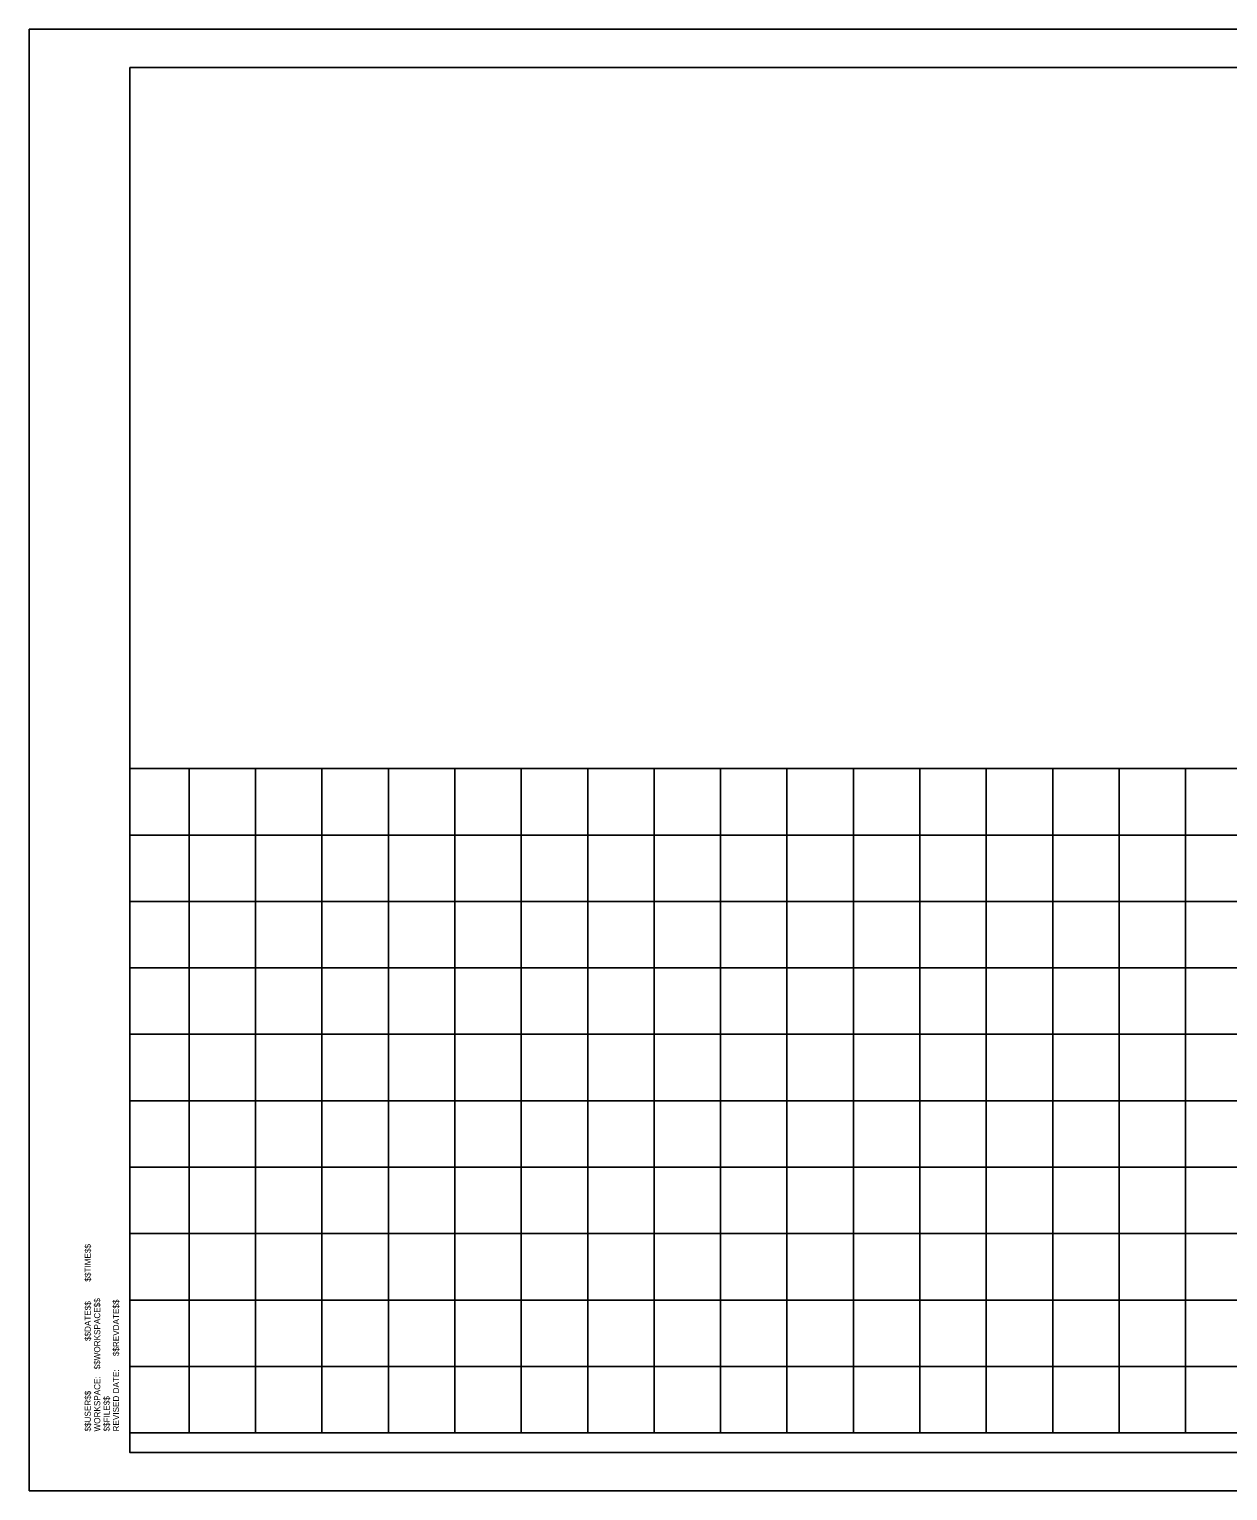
# Model space of a CAD drawing. Extents: x 0 to 1228740, y 0 to 152440.
# Drawn here: x 0 to 18.04, y 0 to 22 of the extents above; entities that cross this region are included whole.
import ezdxf

# ---------------------------------------------------------------- set-up
doc = ezdxf.new("R2010")
doc.units = 0
for name, color, linetype in [('G-TBLK', 7, 'Continuous'), ('R_Border', 7, 'Continuous'), ('R_Grid', 7, 'Continuous'), ('R_No Plot', 7, 'Continuous')]:
    doc.layers.add(name, color=color, linetype=linetype)

msp = doc.modelspace()

# ---------------------------------------------------------------- linework, layer by layer
at = {"layer": 'R_Border'}
for p, q in [((1.516, 21.423), (33.423, 21.423)), ((1.516, 0.577), (1.516, 21.423)), ((33.423, 0.577), (1.516, 0.577))]:
    msp.add_line(p, q, dxfattribs=at)
msp.add_lwpolyline([(34, 22), (0, 22), (0, 0), (34, 0)], close=True, dxfattribs=at)
at = {"layer": 'R_Grid'}
for p, q in [((33.423, 10.871), (1.516, 10.871)), ((2.407, 0.871), (2.407, 10.871)), ((3.407, 0.871), (3.407, 10.871)), ((4.407, 0.871), (4.407, 10.871)), ((5.407, 0.871), (5.407, 10.871)), ((6.407, 0.871), (6.407, 10.871)), ((7.407, 0.871), (7.407, 10.871)), ((8.407, 0.871), (8.407, 10.871)), ((9.407, 0.871), (9.407, 10.871)), ((10.407, 0.871), (10.407, 10.871)), ((11.407, 0.871), (11.407, 10.871)), ((12.407, 0.871), (12.407, 10.871)), ((13.407, 0.871), (13.407, 10.871)), ((14.407, 0.871), (14.407, 10.871)), ((15.407, 0.871), (15.407, 10.871)), ((16.407, 0.871), (16.407, 10.871)), ((17.407, 0.871), (17.407, 10.871)), ((33.423, 9.871), (1.516, 9.871)), ((33.423, 8.871), (1.516, 8.871)), ((33.423, 7.871), (1.516, 7.871)), ((33.423, 6.871), (1.516, 6.871)), ((33.423, 5.871), (1.516, 5.871)), ((33.423, 4.871), (1.516, 4.871)), ((33.423, 3.871), (1.516, 3.871)), ((33.423, 2.871), (1.516, 2.871)), ((33.423, 1.871), (1.516, 1.871)), ((33.423, 0.871), (1.516, 0.871))]:
    msp.add_line(p, q, dxfattribs=at)
at = {"layer": 'R_No Plot'}
for points in [[(27.159, 21.423), (1.516, 21.423), (1.517, 0.575), (33.422, 0.579), (33.422, 17.406), (30.667, 17.405), (30.667, 19.442), (30.667, 20.147), (30.667, 20.435), (27.159, 20.435)], [(1.516, 10.871), (1.516, 0.577), (33.423, 0.577), (33.423, 10.871)]]:
    msp.add_lwpolyline(points, close=True, dxfattribs=at)

# ---------------------------------------------------------------- texts
at = {"layer": 'G-TBLK'}
for s, p in [('$$TIME$$', (0.927, 3.148)), ('$$WORKSPACE$$', (1.069, 1.827)), ('$$REVDATE$$', (1.352, 2.026)), ('$$DATE$$', (0.927, 2.254)), ('REVISED DATE:', (1.352, 0.893)), ('WORKSPACE:', (1.069, 0.892)), ('$$USER$$', (0.927, 0.892)), ('$$FILE$$', (1.211, 0.892))]:
    msp.add_text(s, height=0.0918, rotation=90, dxfattribs=at).set_placement(p)

doc.saveas('drawing.dxf')
